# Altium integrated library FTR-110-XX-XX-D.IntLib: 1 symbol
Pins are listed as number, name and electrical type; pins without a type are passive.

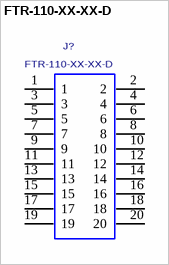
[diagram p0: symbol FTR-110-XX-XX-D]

## FTR-110-XX-XX-D
designator J?
HI-TEMP TERMINAL MICRO-STRIP (DOUBLE ROW).; MANUFACTURER: SAMTEC
footprint FTR-110-XX-XX-D
pins: 1, 2, 3, 4, 5, 6, 7, 8, 9, 10, 11, 12, 13, 14, 15, 16, 17, 18, 19, 20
